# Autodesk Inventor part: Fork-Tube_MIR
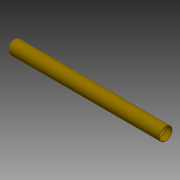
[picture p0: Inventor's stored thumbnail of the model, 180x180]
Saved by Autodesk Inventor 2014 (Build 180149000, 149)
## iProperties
Created: 2001-11
Part Number: Fork-Tube_MIR
Document SubType Name: Modeling
Designer: Autodesk, Inc.
Mass: 63.0746 g
Surface Area: 510.582 cm^2
Volume: 63.0746 cm^3
Density: 1 g/cm^3
Material: Generic
Appearance: Gold
Author: Autodesk, Inc.
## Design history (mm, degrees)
derived "Fork-Tube.ipt"
body "Solid1"
tag "TaggingFeature2"
feature "DerivedBody::Fork-Tube.ipt" dims "d0" = 10
